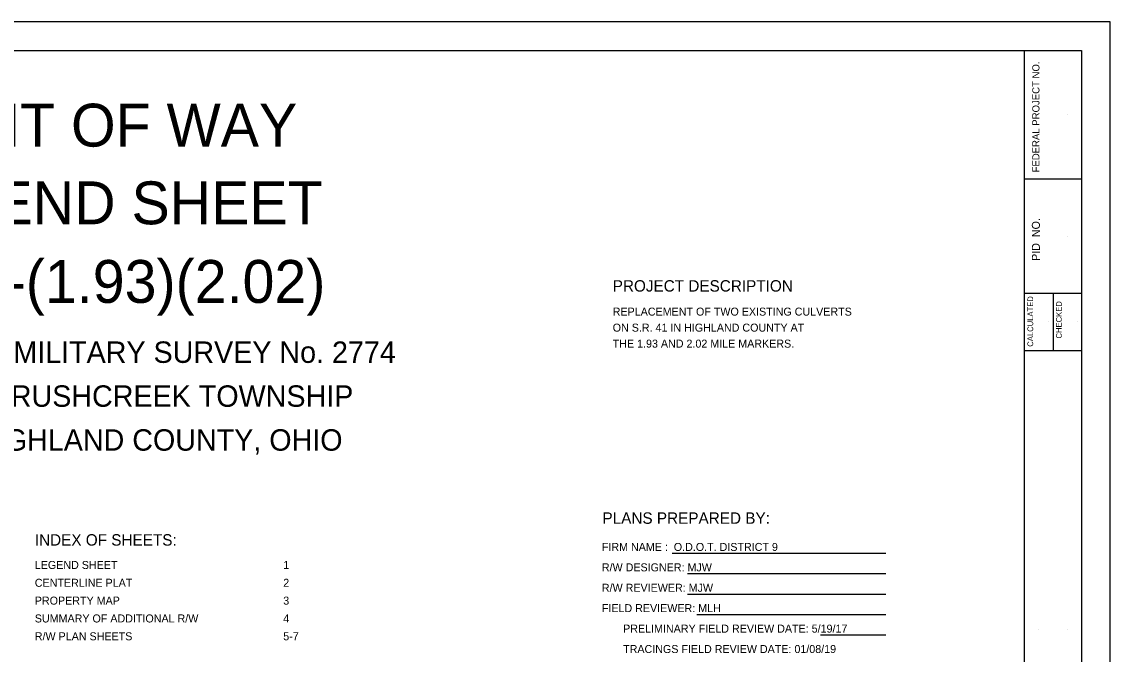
# Model space of a CAD drawing. Extents: x -0.4 to 33.6, y -0.9 to 21.1.
# Drawn here: x 14.55 to 33.59, y 10.01 to 21.08 of the extents above; entities that cross this region are included whole.
import ezdxf

# ---------------------------------------------------------------- set-up
doc = ezdxf.new("R2010")
doc.units = 0
for name, color, linetype in [('SH_Border', 7, 'Continuous'), ('SH_Cut_Line', 7, 'Continuous'), ('SH_Data', 7, 'Continuous'), ('SH_Text', 7, 'Continuous')]:
    doc.layers.add(name, color=color, linetype=linetype)

msp = doc.modelspace()

# ---------------------------------------------------------------- linework, layer by layer
at = {"layer": 'SH_Border'}
for p, q in [((32.087, -0.423), (32.087, 20.577)), ((32.087, 18.327), (33.087, 18.327)), ((32.087, 16.327), (33.087, 16.327)), ((32.087, 16.327), (33.087, 16.327)), ((32.587, 16.327), (32.587, 15.327)), ((32.087, 15.327), (33.087, 15.327))]:
    msp.add_line(p, q, dxfattribs=at)
msp.add_lwpolyline([(1.587, 20.577), (33.087, 20.577), (33.087, -0.423), (1.587, -0.423)], close=True, dxfattribs=at)
at = {"layer": 'SH_Cut_Line'}
msp.add_lwpolyline([(-0.413, -0.923), (33.587, -0.923), (33.587, 21.077), (-0.413, 21.077)], close=True, dxfattribs=at)
at = {"layer": 'SH_Data'}
for p, q in [((32.837, 19.452), (32.837, 19.452)), ((32.837, 17.327), (32.837, 17.327)), ((32.507, 15.831), (32.507, 15.831)), ((33.007, 15.831), (33.007, 15.831)), ((32.333, 10.452), (32.333, 10.452)), ((32.837, 10.452), (32.837, 10.452))]:
    msp.add_line(p, q, dxfattribs=at)
at = {"layer": 'SH_Text'}
for p, q in [((25.928, 11.779), (29.665, 11.779)), ((26.192, 11.422), (29.665, 11.422)), ((26.192, 11.065), (29.665, 11.065)), ((26.356, 10.708), (29.665, 10.708)), ((28.519, 10.35), (29.665, 10.35))]:
    msp.add_line(p, q, dxfattribs=at)

# ---------------------------------------------------------------- texts
at = {"layer": 'SH_Data'}
for s, height, p in [('FEDERAL PROJECT NO.', 0.125, (32.349, 18.441)), ('PID  NO.', 0.14, (32.357, 16.893)), ('CALCULATED', 0.1, (32.239, 15.392)), ('CHECKED', 0.1, (32.739, 15.535))]:
    msp.add_text(s, height=height, rotation=90, dxfattribs=at).set_placement(p)
for s, height, p in [('PROJECT DESCRIPTION', 0.2, (24.886, 16.356)), ('REPLACEMENT OF TWO EXISTING CULVERTS', 0.14, (24.886, 15.936)), ('ON S.R. 41 IN HIGHLAND COUNTY AT', 0.14, (24.886, 15.656)), ('THE 1.93 AND 2.02 MILE MARKERS.', 0.14, (24.886, 15.376))]:
    msp.add_text(s, height=height, dxfattribs=at).set_placement(p)
at = {"layer": 'SH_Text'}
for s, height, p in [('RIGHT OF WAY', 0.75, (12.014, 18.893)), ('LEGEND SHEET', 0.75, (12.067, 17.534)), ('HIG-41-(1.93)(2.02)', 0.75, (11.055, 16.159)), ('VIRGINIA MILITARY SURVEY No. 2774', 0.375, (12.063, 15.109)), ('BRUSHCREEK TOWNSHIP', 0.375, (14.025, 14.341)), ('HIGHLAND COUNTY, OHIO', 0.375, (13.753, 13.573)), ('PLANS PREPARED BY:', 0.2, (24.707, 12.294)), ('INDEX OF SHEETS:', 0.2, (14.779, 11.912)), ('FIRM NAME :  O.D.O.T. DISTRICT 9', 0.14, (24.696, 11.819)), ('LEGEND SHEET', 0.14, (14.779, 11.504)), ('1', 0.14, (19.124, 11.504)), ('R/W DESIGNER: MJW', 0.14, (24.696, 11.462)), ('CENTERLINE PLAT', 0.14, (14.779, 11.192)), ('2', 0.14, (19.124, 11.192)), ('R/W REVIEWER: MJW', 0.14, (24.696, 11.105)), ('PROPERTY MAP', 0.14, (14.779, 10.88)), ('3', 0.14, (19.124, 10.88)), ('FIELD REVIEWER: MLH', 0.14, (24.696, 10.748)), ('SUMMARY OF ADDITIONAL R/W', 0.14, (14.779, 10.568)), ('4', 0.14, (19.124, 10.568)), ('PRELIMINARY FIELD REVIEW DATE: 5/19/17', 0.14, (25.068, 10.39)), ('R/W PLAN SHEETS', 0.14, (14.779, 10.256)), ('5-7', 0.14, (19.124, 10.256)), ('TRACINGS FIELD REVIEW DATE: 01/08/19', 0.14, (25.068, 10.033))]:
    msp.add_text(s, height=height, dxfattribs=at).set_placement(p)

doc.saveas('drawing.dxf')
